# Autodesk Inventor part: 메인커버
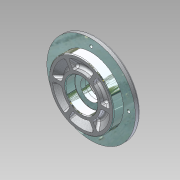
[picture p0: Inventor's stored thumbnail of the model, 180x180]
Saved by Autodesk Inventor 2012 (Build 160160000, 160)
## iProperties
Manager: KYOUNG IL JANG
Company: 한국ATC센터
Created: 2012-10
Part Number: 메인커버
Document SubType Name: Modeling
Density: 1 g/cm^3
Checked By: KYOUNG IL JANG
Vendor: CBT Solutions
Designer: KYOUNG IL JANG
Material: 기본값
Author: KYOUNG IL JANG
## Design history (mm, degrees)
sketch "스케치1"
  geometry: L1 (0, 0)-(0, 28.5); L2 (0, 0)-(28.5, 0); L3 (28.5, 0)-(28.5, 4.726); L4 (28.5, 8)-(31.774, 8); L5 (32.966, 8)-(33.879, 7.234); L6 (42.5, 0)-(47.5, 0); L7 (47.5, 0)-(47.5, 14.5); L8 (47.5, 14.5)-(65, 14.5); L9 (65, 14.5)-(65, 22.5); L10 (65, 22.5)-(33.464, 22.5); L11 (33.464, 22.5)-(30, 28.5); L12 (30, 28.5)-(0, 28.5); L13 (28.5, 4.726)-(28.5, 8); L14 (31.774, 8)-(32.966, 8); L15 (33.879, 7.234)-(42.5, 0); L16 (23.5, 0)-(23.5, 14); L17 (23.5, 14)-(15, 14); L18 (15, 14)-(15, 20.5); L19 (15, 20.5)-(17.5, 20.5); L20 (17.5, 20.5)-(17.5, 28.5); A1 r 3.274 centre (31.774, 4.726) between (33.879, 7.234) and (28.5, 4.726)
  constraints: 40 end point, 11 parallel, 6 perpendicular, 6 tangent, 3 point on circle, 2 collinear, 2 point on line, 1 centre point, 1 vertical
  dimensions: "d1" = 130 diameter of L9 L1; "d2" = 95 diameter of L7 L1; "d3" = 57 diameter of L3 L1; "d4" = 5 distance of L6.start L6.end; "d5" = 14.5 distance between parallel lines of L8 L6; "d6" = 8 distance of L8.end L9.end; "d7" = 6 distance between parallel lines of L10 L12; "d8" = 8 distance of L2.end L4.start; "d9" = 140 deg angle of L6 L5; "d10" = 47 diameter of L16 L1; "d11" = 14 distance of L16.start L16.end; "d12" = 35 diameter of L20 L1; "d13" = 8 distance of L19.end L20.end; "d14" = 30 diameter of L18 L1; "d15" = 120 deg angle of L10 L11; "d16" = 60 diameter of L11.end L1
revolve "회전1" sketch "스케치1" stored, may be unused: angle "d17" = 90 deg
sketch "스케치2"
  geometry: L1 (28.5, 0)-(42.5, 0); 3 further points
  constraints: 2 end point, 2 horizontal alignment, 1 horizontal, 1 point on line, 2 other
feature "리브1" sketch "스케치2" dims "d18" = 5, "d19" = 1, "d20" = 0
fillet "모깎기1" dims "d21" = 3
fillet "모깎기2" dims "d25" = 3, "d26" = 0.3
chamfer "모따기1" distance "d27" = 1; stored, may be unused: second distance "d28" = 2, angle "d29" = 45 deg
sketch "스케치3"
  geometry: C1 r 2.067 at (55, 0) reference; C2 r 2.067 at (0, -55) reference; C3 r 2.067 at (-55, 0) reference; C4 r 2.067 at (0, 55) reference; 1 further point
hole "구멍1" sketch "스케치3" at (0, 55), (-55, 0), (0, -55), (55, 0) diameter "d30" = 4.5; stored, may be unused: countersink angle "d34" = 90 deg, drill point angle "d36" = 118 deg; dims "d31" = 6, "d32" = 8, "d33" = 4.4, "d35" = 8
node "솔리드1"
pattern_circular "원형 패턴1" dims angle "d23" = 360 deg
node "참조1"
node "참조2"
node "참조3"
node "참조4"
